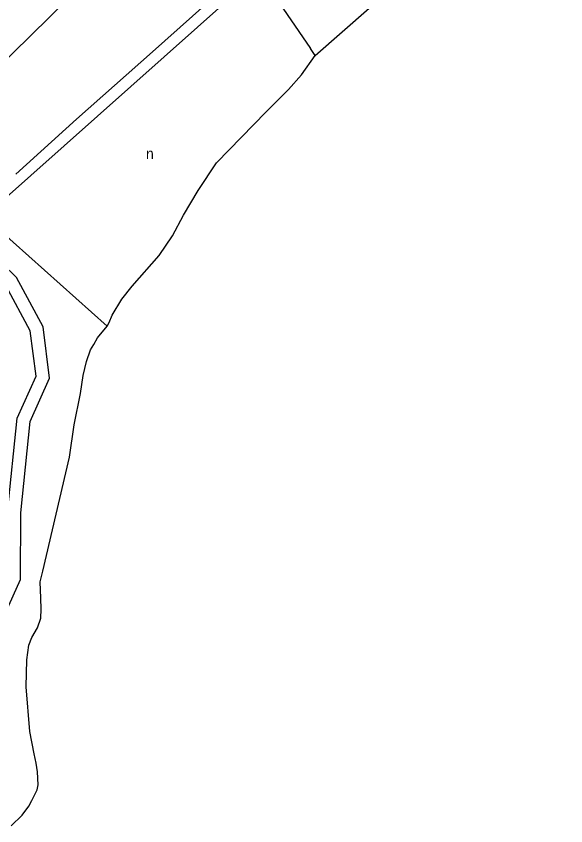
# Model space of a CAD drawing. Extents: x 161773 to 163836, y 384796 to 386521.
# Drawn here: x 162928.2 to 163135.5, y 385605.3 to 385910.7 of the extents above; entities that cross this region are included whole.
import ezdxf

# ---------------------------------------------------------------- set-up
doc = ezdxf.new("R2010")
doc.units = 0
doc.layers.add('BLT_Basislijn', color=7, linetype='Continuous')
doc.layers.add('BLT_Centroide', color=7, linetype='Continuous')

msp = doc.modelspace()

# ---------------------------------------------------------------- linework, layer by layer
at = {"layer": 'BLT_Basislijn'}
for p, q in [((163019.64, 385927.14), (162920.05, 385838.41)), ((163019.64, 385927.14), (163039.27, 385898.46)), ((163041.05, 385895.86), (163039.27, 385898.46)), ((162962.58, 385793.83), (162916.31, 385834.96))]:
    msp.add_line(p, q, dxfattribs=at)
for points in [[(163041.05, 385895.86), (163061.31, 385913.73), (163077.4, 385926.76), (163115.47, 385955.24), (163135.53, 385969.74)], [(162979.35, 385965.99), (162976.33, 385962.44), (162975.37, 385959.76), (162976.25, 385956.51), (162981.78, 385950.68), (162913.19, 385883.34), (162894.24, 385902.64), (162935.23, 385942.39)], [(163009.84, 385924.25), (162979.58, 385897.28)], [(162979.58, 385897.28), (162950.98, 385871.8), (162928.15, 385851.15)], [(162962.58, 385793.83), (162963.26, 385795.12), (162964.49, 385797.86), (162968.09, 385803.91), (162972.03, 385808.85), (162982.15, 385820.45), (162987.18, 385827.79), (162991.36, 385835.65), (162996.87, 385844.89), (163003.81, 385855.36), (163022.53, 385874.57), (163030.99, 385883.02), (163035.79, 385888.53), (163041.05, 385895.86)], [(162913.47, 385674.18), (162924.84, 385699.32), (162924.99, 385723.61), (162928.64, 385759.06), (162935.7, 385774.94), (162933.54, 385791.98), (162924.29, 385809.05), (162887.23, 385845.17), (162834.81, 385879.19), (162829.21, 385883.72)], [(162917.55, 385671.06), (162929.83, 385698.23), (162929.98, 385723.33), (162933.53, 385757.76), (162940.83, 385774.19), (162938.38, 385793.54), (162928.32, 385812.1), (162890.36, 385849.1)], [(162926.33, 385605.29), (162930.48, 385609.33), (162933, 385612.76), (162934.12, 385614.78), (162936.1, 385618.85), (162936.48, 385620.71), (162936.32, 385625.63), (162935.81, 385628.95), (162935, 385632.5), (162933.4, 385640.83), (162931.95, 385657.75), (162932.28, 385667.92), (162933.05, 385673.49), (162934.15, 385676.37), (162936.27, 385679.99), (162937.52, 385683.58), (162937.59, 385687.05), (162937.58, 385691.11), (162937.33, 385697.29), (162938.31, 385701.35), (162948.3, 385744.39), (162950.06, 385756.57), (162952.51, 385768.41), (162953.52, 385775.19), (162954.73, 385780.44), (162956.31, 385784.8), (162957.46, 385786.86), (162958.94, 385789.31), (162962.58, 385793.83)]]:
    msp.add_lwpolyline(points, dxfattribs=at)

# ---------------------------------------------------------------- texts
at = {"layer": 'BLT_Centroide'}
msp.add_text('n', height=4, dxfattribs=at).set_placement((162977.15, 385856.86))

doc.saveas('drawing.dxf')
